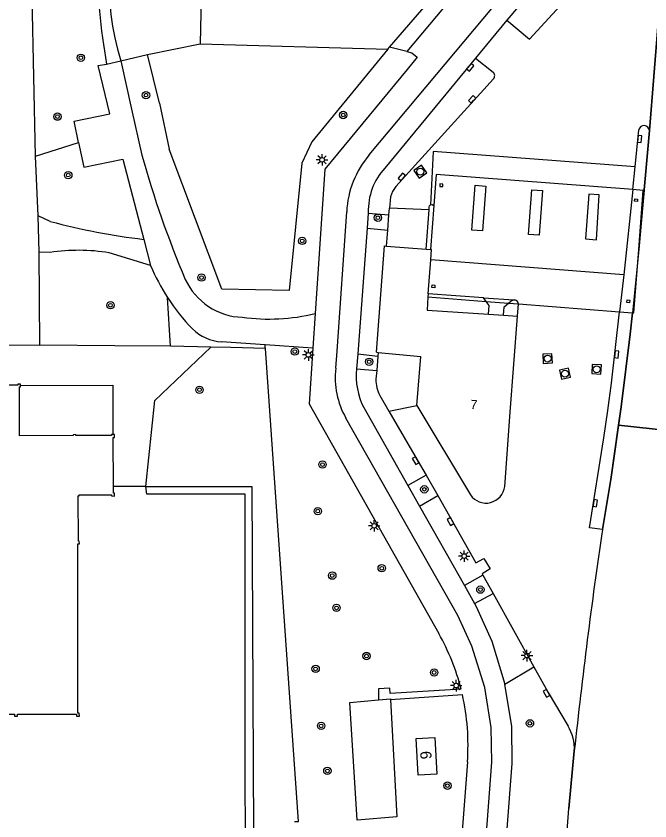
# Model space of a CAD drawing. Extents: x 132573 to 132944, y 398226 to 398676.
# Drawn here: x 132682.1 to 132750.7, y 398350.8 to 398438.1 of the extents above; entities that cross this region are included whole.
import ezdxf

# ---------------------------------------------------------------- set-up
doc = ezdxf.new("R2010")
doc.units = 0
for name, color, linetype in [('gg-afsc-hekwerk', 7, 'Continuous'), ('gg-anno-huisnummerreeks BGT', 7, 'Continuous'), ('gg-bbg-hoofdgebouw', 7, 'Continuous'), ('gg-bbg-luifel en loopbrug', 7, 'Continuous'), ('gg-bbg-pilaar overkapping', 7, 'Continuous'), ('gg-knt-verharding', 7, 'Continuous'), ('gg-knt-verharding nz', 7, 'Continuous'), ('gt-anno-plantopografie huisnummer', 7, 'Continuous'), ('gt-bbg-plantopografie pand', 7, 'Continuous'), ('gt-grn-groengrens', 7, 'Continuous'), ('gt-grn-vlakafsluiter', 7, 'Continuous'), ('gt-symb-boom', 7, 'Continuous'), ('gt-symb-kolk', 7, 'Continuous'), ('gt-symb-lichtmast', 7, 'Continuous'), ('gt-symb-rioolschacht', 7, 'Continuous'), ('ir-asfa-asfalt arcering', 7, 'Continuous')]:
    doc.layers.add(name, color=color, linetype=linetype)

msp = doc.modelspace()

# ---------------------------------------------------------------- linework, layer by layer
at = {"layer": 'gg-afsc-hekwerk'}
for p, q in [((132722.531, 398434.712), (132730.928, 398444.465)), ((132702.121, 398440.197), (132702.019, 398435.041)), ((132702.019, 398435.041), (132722.335, 398434.485)), ((132722.335, 398434.485), (132722.531, 398434.712)), ((132703.147, 398402.191), (132698.789, 398402.28)), ((132709.066, 398402.041), (132709.058, 398402.153)), ((132710.122, 398386.981), (132709.066, 398402.041))]:
    msp.add_line(p, q, dxfattribs=at)
for points in [[(132604.511, 398403.424), (132608.788, 398403.371), (132617.481, 398403.23), (132626.206, 398403.178), (132635.061, 398402.95), (132641.245, 398402.951), (132661.988, 398402.675), (132670.216, 398402.551), (132684.626, 398402.413)], [(132698.789, 398402.28), (132692.756, 398402.32), (132684.626, 398402.413)], [(132709.066, 398402.041), (132705.321, 398402.147), (132703.147, 398402.191)], [(132682.553, 398398.031), (132692.547, 398398.051), (132692.533, 398392.716)], [(132712.22, 398350.77), (132712.662, 398350.77), (132710.122, 398386.981)], [(132722.617, 398364), (132723.297, 398351.292), (132719, 398350.897), (132718.232, 398363.676), (132721.316, 398363.943)], [(132721.316, 398363.943), (132722.614, 398364.055), (132722.617, 398364)]]:
    msp.add_lwpolyline(points, dxfattribs=at)
at = {"layer": 'gg-bbg-hoofdgebouw'}
for p, q in [((132722.188, 398413.132), (132726.472, 398412.81)), ((132726.472, 398412.81), (132726.952, 398412.774)), ((132726.708, 398407.975), (132726.973, 398411.661)), ((132726.682, 398407.621), (132726.58, 398406.2)), ((132726.708, 398407.975), (132726.682, 398407.621)), ((132726.58, 398406.2), (132733.224, 398405.746)), ((132733.224, 398405.746), (132734.851, 398405.635)), ((132734.851, 398405.635), (132736.39, 398405.53)), ((132735.59, 398395.13), (132736.39, 398405.53)), ((132721.12, 398401.63), (132721.279, 398401.615)), ((132721.279, 398401.615), (132725.913, 398401.179)), ((132725.459, 398395.867), (132725.913, 398401.179)), ((132725.459, 398395.867), (132731.275, 398386.175)), ((132734.997, 398387.097), (132735.59, 398395.13))]:
    msp.add_line(p, q, dxfattribs=at)
for points in [[(132721.12, 398401.63), (132721.986, 398413.147), (132722.188, 398413.132)], [(132726.973, 398411.661), (132727.052, 398412.766), (132726.952, 398412.774)], [(132682.553, 398398.031), (132682.557, 398398.172), (132682.276, 398398.179), (132682.276, 398398.071), (132675.719, 398398.07), (132675.719, 398398.185), (132675.434, 398398.19), (132675.435, 398398.07), (132669.151, 398398.07), (132669.153, 398398.181), (132668.839, 398398.185), (132668.833, 398397.675), (132669.023, 398397.674)], [(132692.533, 398392.716), (132692.394, 398392.719), (132692.394, 398392.604), (132688.551, 398392.597), (132688.551, 398392.703), (132688.262, 398392.696), (132688.262, 398392.597), (132682.447, 398392.587), (132682.434, 398397.868), (132682.549, 398397.868), (132682.553, 398398.031)], [(132692.61, 398387.061), (132692.592, 398392.405), (132692.716, 398392.406), (132692.714, 398392.712), (132692.533, 398392.716)], [(132678.362, 398362.387), (132681.915, 398362.389), (132681.916, 398362.198), (132682.212, 398362.199), (132682.212, 398362.389), (132688.613, 398362.393), (132688.613, 398362.195), (132688.922, 398362.197), (132688.92, 398362.516), (132688.751, 398362.516), (132688.746, 398380.873), (132688.924, 398380.873), (132688.921, 398381.17), (132688.815, 398381.169), (132688.78, 398386.056), (132688.897, 398386.057), (132688.898, 398386.171), (132692.416, 398386.167), (132692.416, 398386.051), (132692.726, 398386.048), (132692.731, 398386.369), (132692.612, 398386.369), (132692.61, 398387.061)]]:
    msp.add_lwpolyline(points, dxfattribs=at)
msp.add_arc((132732.966, 398387.324), 2.044, 214.20673, 353.61933, dxfattribs=at)
at = {"layer": 'gg-bbg-luifel en loopbrug'}
for p, q in [((132727.305, 398417.539), (132726.952, 398412.774)), ((132726.682, 398407.621), (132732.971, 398407.138)), ((132732.971, 398407.138), (132735.389, 398406.952)), ((132735.389, 398406.952), (132736.479, 398406.868)), ((132736.479, 398406.868), (132747.436, 398406.027)), ((132747.436, 398406.027), (132748.835, 398405.92))]:
    msp.add_line(p, q, dxfattribs=at)
for points in [[(132748.857, 398419.26), (132727.553, 398420.883), (132727.305, 398417.539)], [(132749.5, 398412.772), (132750.001, 398419.173), (132748.857, 398419.26)], [(132748.835, 398405.92), (132748.964, 398405.91), (132749.5, 398412.772)]]:
    msp.add_lwpolyline(points, dxfattribs=at)
at = {"layer": 'gg-bbg-pilaar overkapping'}
for points in [[(132727.97, 398419.867), (132727.963, 398419.593), (132728.28, 398419.585), (132728.288, 398419.858), (132727.97, 398419.867)], [(132749.046, 398418.008), (132749.074, 398418.264), (132749.382, 398418.23), (132749.354, 398417.975), (132749.046, 398418.008)], [(132727.14, 398408.926), (132727.437, 398408.902), (132727.413, 398408.61), (132727.116, 398408.635), (132727.14, 398408.926)], [(132748.23, 398407.026), (132748.26, 398407.312), (132748.543, 398407.282), (132748.512, 398406.995), (132748.23, 398407.026)]]:
    msp.add_lwpolyline(points, dxfattribs=at)
at = {"layer": 'gg-knt-verharding'}
for p, q in [((132732.612, 398444.051), (132724.408, 398434.238)), ((132737.682, 398435.563), (132742.399, 398440.745)), ((132735.225, 398437.616), (132731.842, 398433.513)), ((132735.225, 398437.616), (132737.682, 398435.563)), ((132724.408, 398434.238), (132722.531, 398434.712)), ((132731.842, 398433.513), (132722.011, 398421.597)), ((132731.842, 398433.513), (132733.735, 398431.99)), ((132691.869, 398432.856), (132693.4, 398433.22)), ((132749.11, 398421.714), (132749.512, 398425.739)), ((132750.659, 398425.658), (132749.5, 398412.772)), ((132748.857, 398419.26), (132749.11, 398421.714)), ((132722.455, 398416.527), (132722.511, 398417.239)), ((132726.792, 398417.061), (132722.511, 398417.239)), ((132726.472, 398412.81), (132726.792, 398417.061)), ((132685.778, 398415.811), (132684.461, 398416.408)), ((132716.83, 398401.739), (132717.88, 398416.856)), ((132720.215, 398416.718), (132720.09, 398415.066)), ((132720.219, 398416.777), (132720.215, 398416.718)), ((132720.215, 398416.718), (132722.455, 398416.527)), ((132722.324, 398414.855), (132722.455, 398416.527)), ((132720.09, 398415.066), (132719.067, 398401.445)), ((132720.09, 398415.066), (132722.324, 398414.855)), ((132722.188, 398413.132), (132722.324, 398414.855)), ((132695.897, 398413.868), (132696.631, 398411.027)), ((132685.751, 398412.441), (132684.577, 398412.465)), ((132696.631, 398411.027), (132692.145, 398412.404)), ((132736.39, 398405.53), (132736.479, 398406.868)), ((132714.462, 398405.826), (132714.209, 398402.084)), ((132748.835, 398405.92), (132748.578, 398403.587)), ((132709.038, 398402.433), (132704.324, 398402.752)), ((132714.209, 398402.084), (132709.038, 398402.433)), ((132716.702, 398399.902), (132716.83, 398401.739)), ((132719.067, 398401.445), (132718.945, 398399.818)), ((132719.067, 398401.445), (132721.246, 398401.2)), ((132721.246, 398401.2), (132721.125, 398399.651)), ((132721.279, 398401.615), (132721.246, 398401.2)), ((132718.945, 398399.818), (132721.125, 398399.651)), ((132721.125, 398399.651), (132721.05, 398398.7)), ((132721.479, 398396.941), (132722.438, 398395.257)), ((132719.724, 398395.629), (132724.501, 398387.18)), ((132722.438, 398395.257), (132725.459, 398395.867)), ((132726.478, 398388.294), (132724.501, 398387.18)), ((132726.478, 398388.294), (132727.73, 398386.095)), ((132724.501, 398387.18), (132725.765, 398384.945)), ((132725.765, 398384.945), (132727.73, 398386.095)), ((132727.73, 398386.095), (132731.874, 398378.818)), ((132725.765, 398384.945), (132730.631, 398376.339)), ((132732.619, 398377.475), (132730.631, 398376.339)), ((132732.619, 398377.475), (132733.727, 398375.483)), ((132730.631, 398376.339), (132731.733, 398374.389)), ((132731.733, 398374.389), (132733.727, 398375.483)), ((132733.727, 398375.483), (132738.143, 398367.547)), ((132735.014, 398365.672), (132738.143, 398367.547)), ((132722.617, 398364), (132730.406, 398364.528)), ((132742.53, 398358.428), (132741.941, 398352.181)), ((132730.95, 398357.232), (132726.705, 398300.532)), ((132738.257, 398303.137), (132741.941, 398352.181))]:
    msp.add_line(p, q, dxfattribs=at)
for points in [[(132720.315, 398423.017), (132733.766, 398439.123), (132735.998, 398441.882), (132737.684, 398444.526), (132738.989, 398447.249), (132740.356, 398451.259), (132741.284, 398455.616), (132741.646, 398459.349), (132741.658, 398474.356), (132741.312, 398479.144), (132740.556, 398483.664), (132739.387, 398488.025), (132737.47, 398493.381)], [(132752.555, 398450.718), (132751.599, 398437.386), (132750.659, 398425.658)], [(132739.493, 398443.403), (132737.517, 398440.383), (132735.225, 398437.616)], [(132724.408, 398434.238), (132724.946, 398434.09), (132725.513, 398433.603), (132724.442, 398432.293)], [(132688.837, 398424.367), (132688.354, 398426.666), (132692.217, 398427.476), (132690.972, 398432.696), (132691.869, 398432.856)], [(132693.4, 398433.22), (132694.577, 398427.972), (132695.703, 398423.005)], [(132724.442, 398432.293), (132715.52, 398421.49), (132714.462, 398405.826)], [(132733.775, 398431.271), (132723.198, 398419.607), (132722.844, 398419.07), (132722.608, 398418.471), (132722.511, 398417.239)], [(132688.837, 398424.367), (132689.401, 398421.682), (132693.648, 398422.573), (132695.897, 398413.868)], [(132749.11, 398421.714), (132727.225, 398423.376), (132726.936, 398417.591)], [(132726.792, 398417.061), (132726.814, 398417.373), (132726.849, 398417.497), (132726.936, 398417.591)], [(132726.936, 398417.591), (132727.131, 398417.636), (132727.305, 398417.539)], [(132733.224, 398405.746), (132733.296, 398406.711), (132732.971, 398407.138)], [(132734.851, 398405.635), (132734.919, 398406.557), (132735.389, 398406.952)], [(132745.571, 398382.431), (132744.174, 398382.602), (132745.743, 398392.358), (132746.175, 398395.306), (132746.553, 398398.262), (132747.436, 398406.027)], [(132748.578, 398403.587), (132747.607, 398395.706), (132746.483, 398387.846), (132745.571, 398382.431)], [(132714.209, 398402.084), (132713.8, 398396.03), (132727.85, 398371.14)], [(132722.438, 398395.257), (132725.515, 398389.985), (132726.478, 398388.294)], [(132729.327, 398300.53), (132733.597, 398357.194), (132733.533, 398360.949), (132732.834, 398365.306), (132731.432, 398369.771), (132729.923, 398373.082), (132717.795, 398394.491)], [(132707.694, 398318.617), (132706.906, 398318.627), (132706.895, 398386.252), (132696.223, 398386.265)], [(132731.874, 398378.818), (132732.731, 398379.291), (132733.416, 398378.172), (132732.541, 398377.614), (132732.619, 398377.475)], [(132731.733, 398374.389), (132731.867, 398374.152), (132733.587, 398370.315), (132735.014, 398365.672)], [(132738.143, 398367.547), (132739.699, 398364.751), (132741.852, 398361.11)], [(132731.715, 398303.732), (132735.79, 398357.041), (132735.761, 398361.072), (132735.014, 398365.672)], [(132730.264, 398365.115), (132722.588, 398364.642), (132722.553, 398365.212), (132721.338, 398365.158), (132721.316, 398363.943)]]:
    msp.add_lwpolyline(points, dxfattribs=at)
for centre, radius, start, end in [((132722.494, 398441.945), 30.374, 158.02766, 196.69426), ((132770.345, 398446.28), 79.616, 181.37323, 189.70697), ((132733.406, 398431.611), 0.502, 317.34538, 49.0231), ((132750.081, 398425.628), 0.579, 2.95086, 168.97021), ((132800.716, 398452.03), 108.951, 195.45061, 202.96279), ((132728.061, 398416.394), 10.192, 139.46891, 177.40045), ((132726.973, 398417.009), 6.758, 137.24483, 181.96649), ((132704.153, 398484.185), 70.8, 254.95768, 263.30361), ((132688.833, 398392.549), 20.129, 80.52955, 98.80735), ((132717.434, 398419.857), 22.599, 203.00048, 212.99382), ((132706.827, 398412.495), 7.081, 204.80156, 267.95546), ((132717.47, 398419.862), 22.632, 212.95353, 223.90623), ((132709.433, 398426.66), 21.433, 262.33552, 283.57186), ((132704.661, 398407.74), 4.999, 225.61653, 266.13925), ((132725.316, 398398.826), 8.681, 172.88093, 209.95877), ((132726.485, 398399.053), 7.579, 174.20912, 206.86003), ((132724.332, 398398.569), 3.285, 177.70854, 209.70388), ((133367.615, 398291.429), 628.665, 171.676909, 173.882136), ((132706.484, 398359.083), 24.534, 14.2328, 29.43559), ((132706.439, 398359.073), 24.58, 355.70542, 12.82291), ((132737.726, 398358.64), 4.808, 357.46843, 30.90545)]:
    msp.add_arc(centre, radius, start, end, dxfattribs=at)
at = {"layer": 'gg-knt-verharding nz'}
for p, q in [((132748.857, 398419.26), (132747.889, 398410.015)), ((132749.5, 398412.772), (132748.835, 398405.92)), ((132747.889, 398410.015), (132726.973, 398411.661)), ((132747.889, 398410.015), (132747.436, 398406.027)), ((132732.68, 398407.521), (132726.708, 398407.975)), ((132732.971, 398407.138), (132732.68, 398407.521)), ((132732.68, 398407.521), (132735.97, 398407.306)), ((132735.97, 398407.306), (132736.072, 398407.299))]:
    msp.add_line(p, q, dxfattribs=at)
for points in [[(132731.786, 398419.747), (132732.946, 398419.631), (132732.574, 398414.789), (132731.419, 398414.872), (132731.786, 398419.747)], [(132738.733, 398414.313), (132737.578, 398414.394), (132737.94, 398419.249), (132739.094, 398419.166), (132738.733, 398414.313)], [(132745.238, 398418.702), (132744.09, 398418.778), (132743.723, 398413.926), (132744.925, 398413.829), (132745.238, 398418.702)], [(132735.389, 398406.952), (132735.691, 398407.206), (132735.97, 398407.306)]]:
    msp.add_lwpolyline(points, dxfattribs=at)
msp.add_arc((132735.992, 398406.815), 0.49, 6.16202, 80.55702, dxfattribs=at)
at = {"layer": 'gt-bbg-plantopografie pand'}
msp.add_lwpolyline([(132725.52, 398357.783), (132725.413, 398359.78), (132727.41, 398359.887), (132727.624, 398355.893), (132725.627, 398355.786), (132725.52, 398357.783)], dxfattribs=at)
at = {"layer": 'gt-grn-groengrens'}
for p, q in [((132684.182, 398422.897), (132683.677, 398446.095)), ((132696.294, 398433.888), (132702.019, 398435.041)), ((132693.4, 398433.22), (132696.294, 398433.888)), ((132697.618, 398428.61), (132696.294, 398433.888)), ((132697.618, 398428.61), (132698.664, 398423.626)), ((132684.182, 398422.897), (132688.837, 398424.367)), ((132684.461, 398416.408), (132684.182, 398422.897)), ((132684.626, 398402.413), (132684.577, 398412.465)), ((132698.789, 398402.28), (132698.479, 398407.551)), ((132709.058, 398402.153), (132709.038, 398402.433)), ((132696.223, 398386.265), (132696.137, 398387.073))]:
    msp.add_line(p, q, dxfattribs=at)
for points in [[(132722.335, 398434.485), (132714.111, 398424.437), (132713.026, 398422.113), (132711.632, 398408.325), (132704.35, 398408.48), (132698.664, 398423.626)], [(132696.137, 398387.073), (132707.616, 398387.08), (132707.915, 398319.615), (132710.05, 398318.24), (132711.197, 398316.606), (132710.856, 398316.325)]]:
    msp.add_lwpolyline(points, dxfattribs=at)
at = {"layer": 'gt-grn-vlakafsluiter'}
for p, q in [((132684.577, 398412.465), (132684.461, 398416.408)), ((132696.137, 398387.073), (132692.61, 398387.061))]:
    msp.add_line(p, q, dxfattribs=at)
msp.add_lwpolyline([(132696.137, 398387.073), (132697.097, 398396.403), (132703.147, 398402.191)], dxfattribs=at)
at = {"layer": 'gt-symb-boom'}
for centre, radius in [((132689.092, 398433.551), 0.4), ((132689.092, 398433.551), 0.2), ((132696.141, 398429.498), 0.4), ((132696.141, 398429.498), 0.2), ((132686.554, 398427.17), 0.4), ((132686.554, 398427.17), 0.2), ((132717.5, 398427.345), 0.4), ((132717.5, 398427.345), 0.2), ((132687.723, 398420.828), 0.4), ((132687.723, 398420.828), 0.2), ((132721.257, 398416.213), 0.4), ((132721.257, 398416.213), 0.2), ((132713.065, 398413.696), 0.4), ((132713.065, 398413.696), 0.2), ((132702.158, 398409.724), 0.4), ((132702.158, 398409.724), 0.2), ((132692.291, 398406.724), 0.4), ((132692.291, 398406.724), 0.2), ((132712.26, 398401.702), 0.4), ((132712.26, 398401.702), 0.2), ((132720.315, 398400.602), 0.4), ((132720.315, 398400.602), 0.2), ((132701.936, 398397.56), 0.4), ((132701.936, 398397.56), 0.2), ((132715.261, 398389.461), 0.4), ((132715.261, 398389.461), 0.2), ((132726.287, 398386.772), 0.4), ((132726.287, 398386.772), 0.2), ((132714.744, 398384.409), 0.4), ((132714.744, 398384.409), 0.2), ((132721.672, 398378.224), 0.4), ((132716.316, 398377.421), 0.4), ((132721.672, 398378.224), 0.2), ((132716.316, 398377.421), 0.2), ((132732.355, 398375.903), 0.4), ((132732.355, 398375.903), 0.2), ((132716.777, 398373.923), 0.4), ((132716.777, 398373.923), 0.2), ((132720.022, 398368.704), 0.4), ((132720.022, 398368.704), 0.2), ((132714.512, 398367.313), 0.4), ((132714.512, 398367.313), 0.2), ((132727.346, 398366.918), 0.4), ((132727.346, 398366.918), 0.2), ((132715.105, 398361.132), 0.4), ((132715.105, 398361.132), 0.2), ((132737.726, 398361.406), 0.4), ((132737.726, 398361.406), 0.2), ((132715.784, 398356.251), 0.4), ((132715.784, 398356.251), 0.2), ((132728.789, 398354.653), 0.4), ((132728.789, 398354.653), 0.2)]:
    msp.add_circle(centre, radius, dxfattribs=at)
at = {"layer": 'gt-symb-kolk'}
for points in [[(132731.107, 398432.642), (132730.865, 398432.355), (132731.171, 398432.097), (132731.655, 398432.671), (132731.349, 398432.929), (132731.107, 398432.642)], [(132731.603, 398428.909), (132731.854, 398429.187), (132731.557, 398429.455), (132731.055, 398428.899), (132731.352, 398428.631), (132731.603, 398428.909)], [(132749.402, 398424.766), (132749.36, 398424.393), (132749.757, 398424.349), (132749.841, 398425.094), (132749.444, 398425.139), (132749.402, 398424.766)], [(132723.987, 398420.508), (132724.237, 398420.788), (132723.938, 398421.054), (132723.439, 398420.494), (132723.737, 398420.228), (132723.987, 398420.508)], [(132746.913, 398401.423), (132746.871, 398401.05), (132747.268, 398401.005), (132747.353, 398401.75), (132746.955, 398401.796), (132746.913, 398401.423)], [(132725.515, 398389.985), (132725.326, 398390.309), (132724.981, 398390.107), (132725.358, 398389.46), (132725.704, 398389.661), (132725.515, 398389.985)], [(132744.608, 398385.301), (132744.554, 398384.93), (132744.949, 398384.872), (132745.058, 398385.614), (132744.662, 398385.672), (132744.608, 398385.301)], [(132729.288, 398383.381), (132729.102, 398383.706), (132728.755, 398383.508), (132729.127, 398382.857), (132729.474, 398383.056), (132729.288, 398383.381)], [(132739.699, 398364.751), (132739.517, 398365.079), (132739.167, 398364.884), (132739.532, 398364.229), (132739.881, 398364.423), (132739.699, 398364.751)]]:
    msp.add_lwpolyline(points, dxfattribs=at)
at = {"layer": 'gt-symb-lichtmast'}
for p, q in [((132715.209, 398422.732), (132715.209, 398423.107)), ((132714.959, 398422.482), (132714.584, 398422.482)), ((132715.032, 398422.659), (132714.767, 398422.924)), ((132715.032, 398422.305), (132714.767, 398422.04)), ((132715.209, 398422.232), (132715.209, 398421.857)), ((132715.386, 398422.659), (132715.651, 398422.924)), ((132715.651, 398422.04), (132715.386, 398422.305)), ((132715.459, 398422.482), (132715.834, 398422.482)), ((132713.476, 398401.337), (132713.101, 398401.337)), ((132713.549, 398401.514), (132713.284, 398401.779)), ((132713.726, 398401.587), (132713.726, 398401.962)), ((132713.903, 398401.514), (132714.168, 398401.779)), ((132713.976, 398401.337), (132714.351, 398401.337)), ((132713.549, 398401.16), (132713.284, 398400.895)), ((132713.726, 398401.087), (132713.726, 398400.712)), ((132714.168, 398400.895), (132713.903, 398401.16)), ((132720.676, 398382.995), (132720.411, 398383.26)), ((132720.853, 398383.068), (132720.853, 398383.443)), ((132721.03, 398382.995), (132721.295, 398383.26)), ((132720.603, 398382.818), (132720.228, 398382.818)), ((132720.676, 398382.641), (132720.411, 398382.376)), ((132720.853, 398382.568), (132720.853, 398382.193)), ((132721.295, 398382.376), (132721.03, 398382.641)), ((132721.103, 398382.818), (132721.478, 398382.818)), ((132730.347, 398379.535), (132729.972, 398379.535)), ((132730.42, 398379.712), (132730.155, 398379.977)), ((132730.597, 398379.785), (132730.597, 398380.16)), ((132731.039, 398379.977), (132730.774, 398379.712)), ((132730.847, 398379.535), (132731.222, 398379.535)), ((132730.42, 398379.358), (132730.155, 398379.093)), ((132730.597, 398379.285), (132730.597, 398378.91)), ((132730.774, 398379.358), (132731.039, 398379.093)), ((132737.225, 398368.923), (132736.96, 398369.188)), ((132737.402, 398368.996), (132737.402, 398369.371)), ((132737.579, 398368.923), (132737.844, 398369.188)), ((132737.152, 398368.746), (132736.777, 398368.746)), ((132737.225, 398368.569), (132736.96, 398368.304)), ((132737.402, 398368.496), (132737.402, 398368.121)), ((132737.844, 398368.304), (132737.579, 398368.569)), ((132737.652, 398368.746), (132738.027, 398368.746)), ((132729.482, 398365.499), (132729.107, 398365.499)), ((132729.555, 398365.676), (132729.29, 398365.941)), ((132729.732, 398365.749), (132729.732, 398366.124)), ((132729.909, 398365.676), (132730.174, 398365.941)), ((132729.982, 398365.499), (132730.357, 398365.499)), ((132729.555, 398365.322), (132729.29, 398365.057)), ((132729.732, 398365.249), (132729.732, 398364.874)), ((132730.174, 398365.057), (132729.909, 398365.322))]:
    msp.add_line(p, q, dxfattribs=at)
for centre in [(132715.209, 398422.482), (132713.726, 398401.337), (132720.853, 398382.818), (132730.597, 398379.535), (132737.402, 398368.746), (132729.732, 398365.499)]:
    msp.add_circle(centre, 0.25, dxfattribs=at)
at = {"layer": 'gt-symb-rioolschacht'}
for points in [[(132726.553, 398421.068), (132725.995, 398421.898), (132725.165, 398421.34), (132725.723, 398420.51)], [(132740.102, 398401.476), (132739.104, 398401.418), (132739.162, 398400.42), (132740.16, 398400.478)], [(132744.416, 398399.314), (132745.415, 398399.259), (132745.47, 398400.258), (132744.471, 398400.313)], [(132741.902, 398399.898), (132740.924, 398399.686), (132741.136, 398398.708), (132742.114, 398398.92)]]:
    msp.add_lwpolyline(points, close=True, dxfattribs=at)
for centre in [(132725.859, 398421.204), (132739.632, 398400.948), (132741.519, 398399.303), (132744.943, 398399.786)]:
    msp.add_circle(centre, 0.375, dxfattribs=at)
at = {"layer": 'ir-asfa-asfalt arcering'}
for points in [[(132762.875, 398471.194), (132759.208, 398422.644), (132758.445, 398414.448), (132756.454, 398395.814), (132756.281, 398392.746), (132747.325, 398393.731), (132747.607, 398395.706), (132748.578, 398403.587), (132748.835, 398405.92), (132748.964, 398405.91), (132749.5, 398412.772), (132750.659, 398425.658), (132751.599, 398437.386), (132752.555, 398450.718)], [(132745.571, 398382.431), (132746.483, 398387.846), (132747.325, 398393.731), (132756.281, 398392.746), (132756.115, 398389.811), (132756.004, 398385.531), (132756.11, 398381.316), (132756.291, 398377.302), (132756.326, 398374.279), (132756.234, 398372.08), (132750.784, 398300.065), (132750.784, 398300.061), (132750.599, 398297.174), (132750.599, 398297.173), (132737.591, 398297.947)], [(132738.556, 398303.108), (132738.583, 398303.383), (132738.278, 398303.414), (132741.941, 398352.181), (132742.53, 398358.428)]]:
    msp.add_lwpolyline(points, dxfattribs=at)
msp.add_arc((133367.615, 398291.429), 628.665, 171.676909, 173.882136, dxfattribs=at)

# ---------------------------------------------------------------- texts
at = {"layer": 'gg-anno-huisnummerreeks BGT'}
msp.add_text('7', height=1, rotation=355.6, dxfattribs=at).set_placement((132731.247, 398395.486))
at = {"layer": 'gt-anno-plantopografie huisnummer'}
msp.add_text('9', height=1.2, rotation=93.05987, dxfattribs=at).set_placement((132727.081, 398357.545))

doc.saveas('drawing.dxf')
